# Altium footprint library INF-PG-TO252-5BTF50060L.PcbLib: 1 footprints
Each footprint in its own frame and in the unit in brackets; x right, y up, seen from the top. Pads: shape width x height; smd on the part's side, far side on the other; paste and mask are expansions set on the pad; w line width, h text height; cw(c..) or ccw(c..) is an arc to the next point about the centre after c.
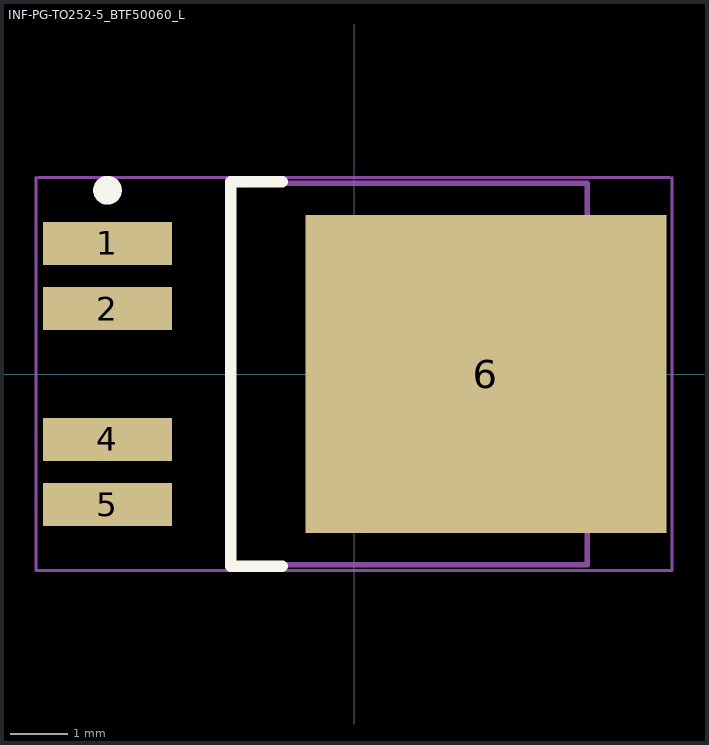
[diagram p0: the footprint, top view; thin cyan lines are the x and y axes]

## INF-PG-TO252-5_BTF50060_L [mm] "DPAK, 5-Leads, Body 6.5x6.12mm, Pitch 1.14mm, IPC High Density"
height 2.35
pads (5):
  rect 2.25x0.75 smd: 1(-4.3,2.28) 2(-4.3,1.14) 4(-4.3,-1.14) 5(-4.3,-2.28)
  rect 6.3x5.55 smd: 6(2.3,0)
Top Overlay:
  circle w0.25: c-4.3,3.205 r0.125
  lines w0.2: -1.25,-3.35 -2.15,-3.35 -2.15,3.35 -1.25,3.35
Mechanical 13:
  lines w0.1: -2.15,-3.325 -2.15,3.325 4.07,3.325 4.07,-3.325 -2.15,-3.325
Mechanical 15:
  lines w0.05: -5.55,3.425 -5.55,-3.425 5.55,-3.425 5.55,3.425 ; -5.5,3.425 5.5,3.425
  lines w0.1: -0.5,0 0.5,0 ; 0,-0.5 0,0.5
3D body: height 2.35, standoff 0, extent -2.15,-3.325 4.07,3.325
